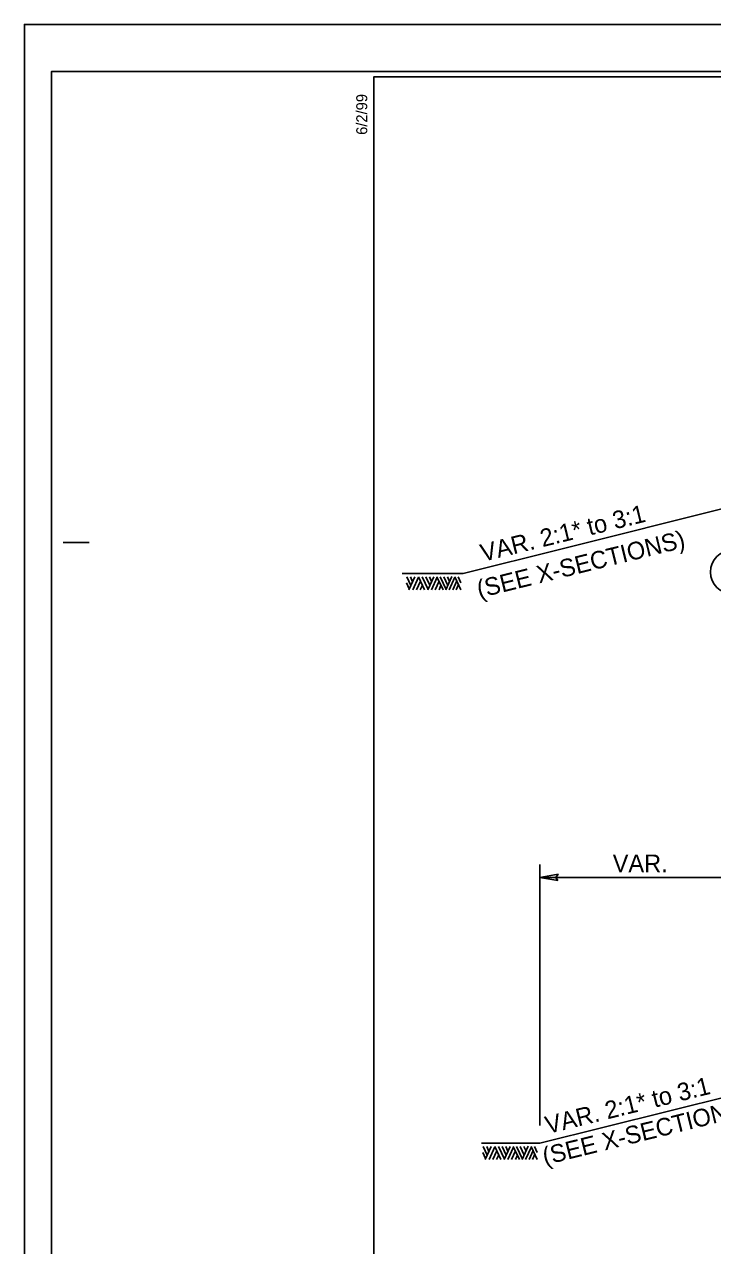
# Model space of a CAD drawing. Extents: x 573687 to 575553, y -54556 to -52223.
# Drawn here: x 573687 to 574016, y -52806 to -52223 of the extents above; entities that cross this region are included whole.
import ezdxf

# ---------------------------------------------------------------- set-up
doc = ezdxf.new("R2010")
doc.units = 0
for name, color, linetype in [('Old_Level_1', 7, 'Continuous'), ('Prop Dimension', 7, 'Continuous'), ('Prop Dimension Text', 7, 'Continuous'), ('Sheet Cutting Line CELL', 7, 'Continuous'), ('Sheet Plot Border Inside CELL', 7, 'Continuous'), ('Sheet Plot Border Outside CELL', 7, 'Continuous'), ('Sheet Typical CELL', 7, 'Continuous'), ('Typical Terminator CELL', 7, 'Continuous'), ('Typical Text Label CELL', 7, 'Continuous')]:
    doc.layers.add(name, color=color, linetype=linetype)

msp = doc.modelspace()

# ---------------------------------------------------------------- linework, layer by layer
at = {"layer": 'Old_Level_1'}
for p, q in [((574023.99, -52453.26), (573944.4, -52473.16)), ((573944.4, -52473.16), (573897.08, -52484.99)), ((573897.08, -52484.99), (573868.01, -52484.99)), ((573871.37, -52492.3), (573869.98, -52489.35)), ((573872.15, -52490.64), (573870.19, -52486.44)), ((573871.2, -52492.7), (573874.08, -52486.44)), ((573872.97, -52488.83), (573871.9, -52486.44)), ((573873.06, -52492.7), (573875.83, -52486.73)), ((573874.84, -52492.7), (573876.73, -52488.63)), ((573878.62, -52492.7), (573875.71, -52486.44)), ((573876.6, -52492.7), (573877.61, -52490.53)), ((573880.32, -52492.52), (573877.51, -52486.44)), ((573881.23, -52490.57), (573879.32, -52486.44)), ((573880.26, -52492.7), (573883.14, -52486.44)), ((573882.04, -52488.76), (573880.98, -52486.44)), ((573881.97, -52492.7), (573884.73, -52486.75)), ((573883.77, -52492.7), (573885.64, -52488.63)), ((573887.54, -52492.7), (573884.6, -52486.44)), ((573885.58, -52492.7), (573886.53, -52490.59)), ((573888.95, -52492.49), (573886.14, -52486.44)), ((573889.79, -52490.69), (573887.83, -52486.44)), ((573888.85, -52492.7), (573891.74, -52486.42)), ((573890.67, -52488.81), (573889.58, -52486.44)), ((573890.41, -52492.7), (573893.21, -52486.63)), ((573892.12, -52492.7), (573894.06, -52488.44)), ((573896.04, -52492.7), (573893.14, -52486.44)), ((573893.76, -52492.7), (573894.89, -52490.23)), ((573896.04, -52489.35), (573894.7, -52486.44)), ((574026.04, -52734.02), (573933.79, -52757.08)), ((573933.79, -52757.08), (573905.87, -52757.08)), ((573908.65, -52762.74), (573906.69, -52758.53)), ((573907.7, -52764.79), (573910.58, -52758.53)), ((573909.47, -52760.92), (573908.4, -52758.53)), ((573909.56, -52764.79), (573912.33, -52758.82)), ((573915.12, -52764.79), (573912.21, -52758.53)), ((573916.82, -52764.62), (573914.01, -52758.53)), ((573917.73, -52762.67), (573915.82, -52758.53)), ((573916.76, -52764.79), (573919.64, -52758.53)), ((573918.54, -52760.85), (573917.48, -52758.53)), ((573918.47, -52764.79), (573921.23, -52758.84)), ((573924.04, -52764.79), (573921.1, -52758.53)), ((573925.45, -52764.58), (573922.64, -52758.53)), ((573926.29, -52762.78), (573924.33, -52758.53)), ((573925.35, -52764.79), (573928.24, -52758.51)), ((573927.17, -52760.9), (573926.08, -52758.53)), ((573926.91, -52764.79), (573929.71, -52758.72)), ((573932.54, -52764.79), (573929.64, -52758.53)), ((573932.54, -52761.44), (573931.2, -52758.53)), ((573907.87, -52764.39), (573906.48, -52761.44)), ((573911.34, -52764.79), (573913.23, -52760.72)), ((573913.11, -52764.79), (573914.11, -52762.63)), ((573920.27, -52764.79), (573922.14, -52760.72)), ((573922.08, -52764.79), (573923.03, -52762.68)), ((573928.62, -52764.79), (573930.56, -52760.54)), ((573930.26, -52764.79), (573931.39, -52762.32))]:
    msp.add_line(p, q, dxfattribs=at)
at = {"layer": 'Prop Dimension'}
for p, q in [((573933.79, -52623.97), (573933.79, -52748.59)), ((574026.04, -52630.11), (573933.79, -52630.11))]:
    msp.add_line(p, q, dxfattribs=at)
at = {"layer": 'Prop Dimension Text'}
msp.add_circle((574025.73, -52484.21), 10.46, dxfattribs=at)
at = {"layer": 'Sheet Cutting Line CELL'}
for p, q in [((575371.43, -52222.67), (573687.43, -52222.67)), ((573687.43, -52222.67), (573687.43, -53322.67))]:
    msp.add_line(p, q, dxfattribs=at)
at = {"layer": 'Sheet Plot Border Inside CELL'}
msp.add_lwpolyline([(575366.93, -52245.12), (573700.43, -52245.12), (573700.43, -53300.22), (575366.93, -53300.22)], close=True, dxfattribs=at)
at = {"layer": 'Sheet Plot Border Outside CELL'}
msp.add_lwpolyline([(575371.43, -52222.67), (573687.43, -52222.67), (573687.43, -53322.67), (575371.43, -53322.67)], close=True, dxfattribs=at)
at = {"layer": 'Sheet Typical CELL'}
msp.add_line((573705.93, -52470.17), (573718.43, -52470.17), dxfattribs=at)
msp.add_lwpolyline([(575354.43, -52247.67), (573854.43, -52247.67), (573854.43, -53297.67), (575354.43, -53297.67)], close=True, dxfattribs=at)
at = {"layer": 'Typical Terminator CELL'}
msp.add_lwpolyline([(573942.4, -52631.59), (573933.79, -52630.11), (573942.45, -52628.58), (573941.35, -52630.11)], close=True, dxfattribs=at)

# ---------------------------------------------------------------- texts
at = {"layer": 'Prop Dimension Text'}
msp.add_text('VAR.', height=8.415, rotation=359.99991, dxfattribs=at).set_placement((573968.6, -52627.57))
at = {"layer": 'Sheet Typical CELL'}
msp.add_text('6/2/99', height=5.25, rotation=90, dxfattribs=at).set_placement((573851.28, -52275.42))
at = {"layer": 'Typical Text Label CELL'}
for s, p in [('VAR. 2:1* to 3:1', (573906.54, -52479.39)), ('(SEE X-SECTIONS)', (573904.85, -52496.73)), ('VAR. 2:1* to 3:1', (573937.52, -52752.66)), ('(SEE X-SECTIONS)', (573936.2, -52767.56))]:
    msp.add_text(s, height=8.415, rotation=13.83992, dxfattribs=at).set_placement(p)

doc.saveas('drawing.dxf')
